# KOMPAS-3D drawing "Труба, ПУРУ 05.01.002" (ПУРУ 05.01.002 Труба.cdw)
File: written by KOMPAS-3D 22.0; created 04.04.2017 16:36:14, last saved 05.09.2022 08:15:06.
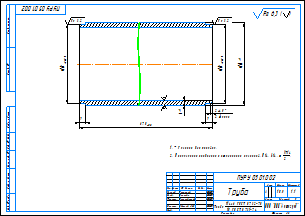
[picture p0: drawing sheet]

Sheet 1: A3, landscape

Document properties: Автор: cons; Полное имя файла: D:\Вован\Антиград\Град\ПУРУ 00.00.000 Установка пусковая ручная Элия-Р\ПУРУ 05.00.000 Корпус\ПУРУ 05.01.000 Обойма\Чертежи\ПУРУ 05.01.002 Труба.cdw; Масса: 10.493033; Знак неуказанной шероховатости: 4; Параметр неуказанной шероховатости: Ra 6,3

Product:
- Part/product: Труба  | designation ПУРУ 05.01.002
    Материал: Труба$d114x6 ГОСТ 8732-78;10 ГОСТ 8731-74$ (density 7856 kg/m3)
    Масса: 10.493033
    Раздел спецификации: Детали
    Форматы листов документа: A3
    source file: ..\ПУРУ 05.01.002 Труба.m3d, ПУРУ 05.01.002 Труба.cdw
- Part/product: (unnamed)  | designation 1
- Part/product: (unnamed)  | designation 2
- Part/product: (unnamed)  | designation 3

Table, sheet 1:
  0;Material:VDE12371B5FDD453AAD3A0896F0FE5778;Sortament:VACA86AD6B524487FA06521D22EE88F1C^SortamentEx:V1A9BFBD95D6C11D7A5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
Title block, sheet 2: Наименование: Труба; designation: ПУРУ 05.01.002; Материал: Труба 114x6 ГОСТ 8732-78 10 ГОСТ 8731-74; Масса: 10,5; sheet number: 1; organisation: ООО "НПЦ"Антиград"; Форматы листов документа: A3; Литера: А; stored path: D:\РУ 00.00.000 Установка противоградовая ручная\РУ 05.00.000 Корпус\РУ 05.01.000 Обойма\Чертежи\РУ 05.01.002 Труба.cdw; Разработал: Грицунов; Проверил: Налоева; Т. контр.: Семеновский; Н. контр.: Абшаев А.М.; Разработал, date: 06.04.2017; Проверил, date: 06.04.2017; Т. контр., date: 06.04.2017; Н. контр., date: 06.04.2017

Views: Вид 1, Местный разрез 1, Спереди
Referenced files in D:\Град\ПУРУ 00.00.000 Установка пусковая ручная Элия-Р\ПУРУ 05.00.000 Корпус\ПУРУ 05.01.000 Обойма\: ПУРУ 05.01.002 Труба.m3d
Referenced files in D:\Вован\Антиград\Град\ПУРУ 00.00.000 Установка пусковая ручная Элия-Р\ПУРУ 05.00.000 Корпус\ПУРУ 05.01.000 Обойма\: ПУРУ 05.01.002 Труба.m3d
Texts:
  Ra 3,2
  Ra 6,3
  Ra 6,3 ( )
  ПУРУ 05.01.002 Труба
Dimensions and other numbers on the sheet: 114; 6; 110; 2; 2 фаски; 9; 678; 1:1; 1; 10,5; 06.04.2017

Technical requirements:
  * Размеры для справок.
  Неуказанные предельные отклонения размеров: H14, h14,    IT14 2 .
